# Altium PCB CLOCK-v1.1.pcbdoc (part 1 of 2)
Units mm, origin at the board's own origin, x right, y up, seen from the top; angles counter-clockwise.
Board outline 180 x 92.5 mm, 2 copper layers (Top Layer, Bottom Layer); 120 components, 111 nets, 414 pads, 6 vias.
Unrouted connection lines stored in the file: 2.
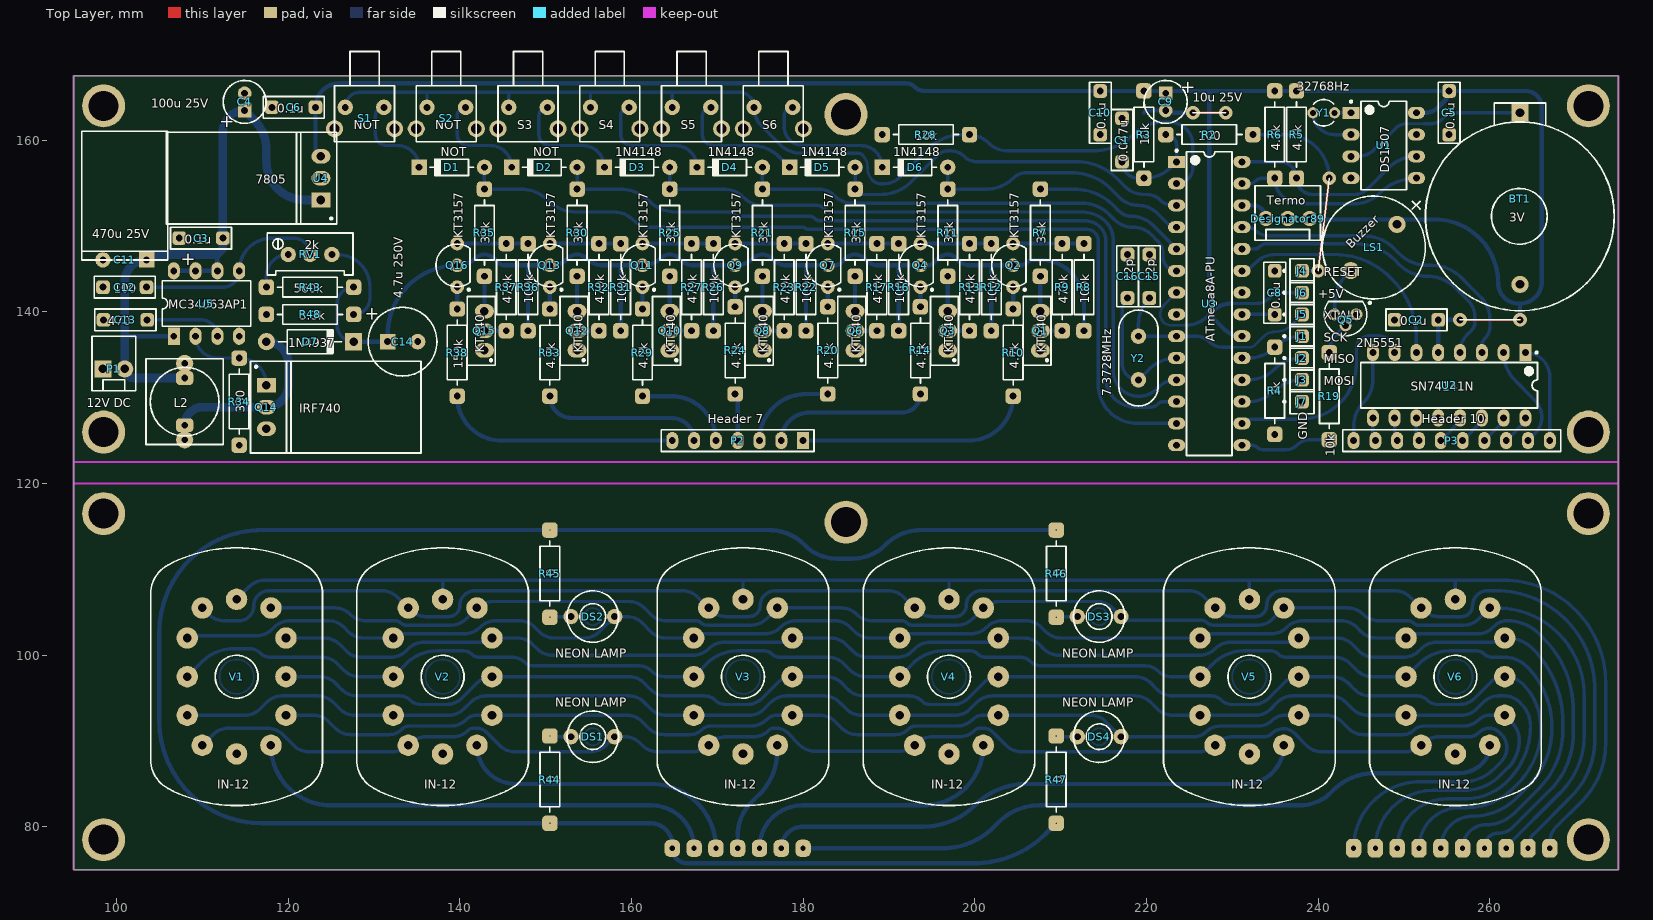
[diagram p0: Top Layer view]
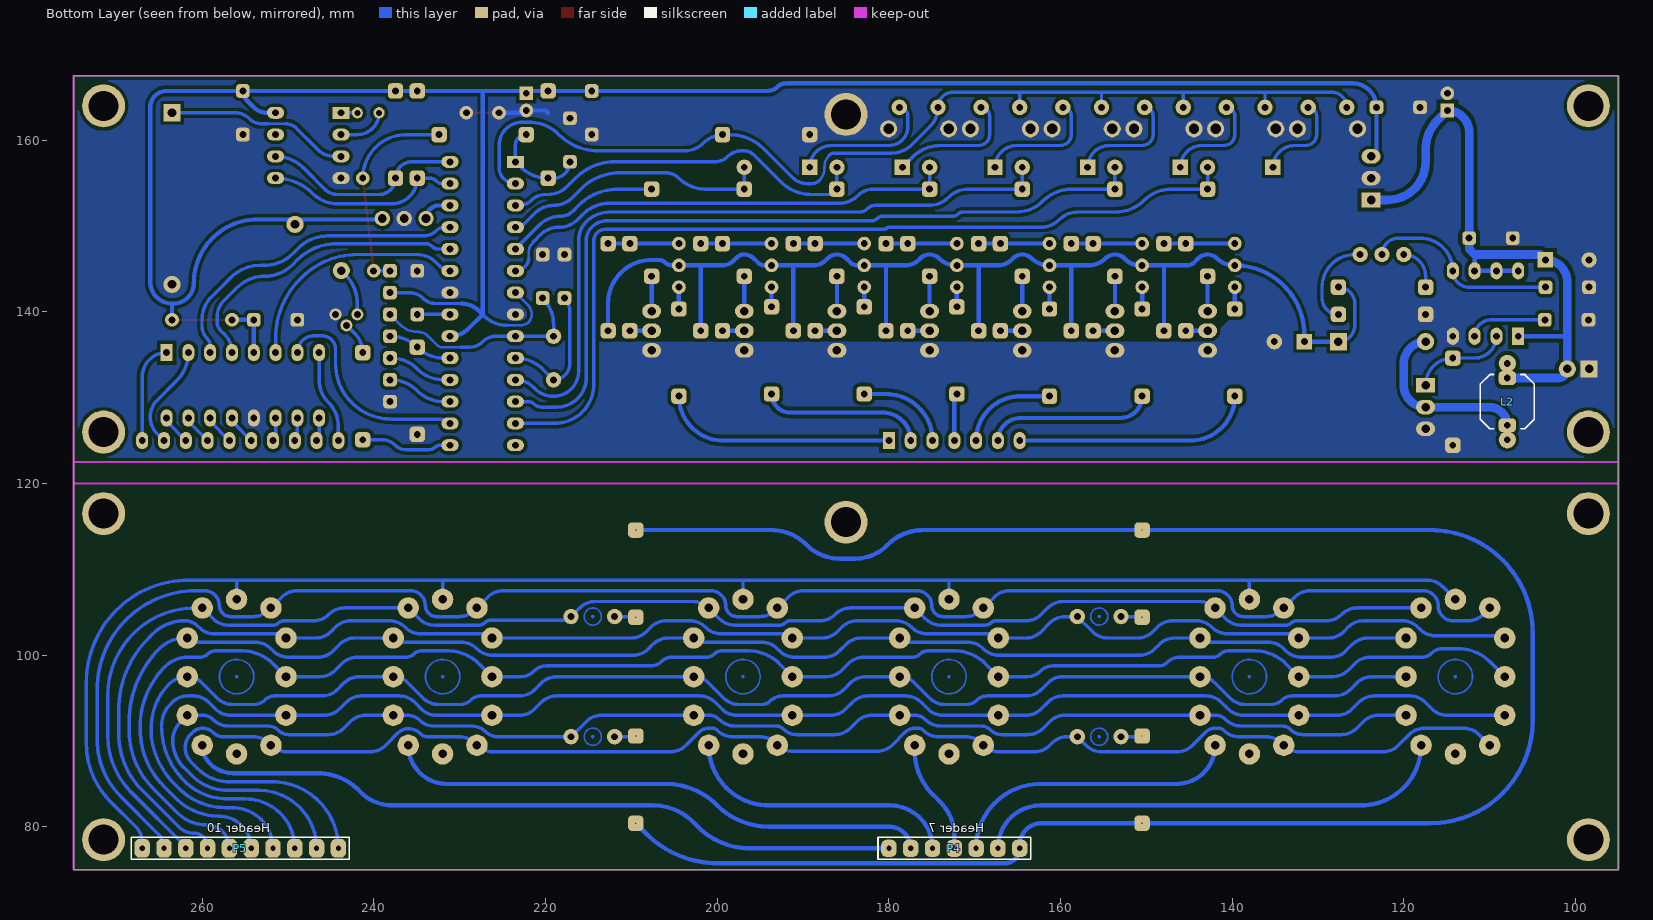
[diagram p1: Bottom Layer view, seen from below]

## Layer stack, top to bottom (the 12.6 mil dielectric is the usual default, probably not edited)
Top Layer: signal copper 0.0356
Dielectric: dielectric 0.32, FR-4, Dk 4.8
Bottom Layer: signal copper 0.0356

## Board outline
95,120 95,122.5 95,167.5 275,167.5 275,122.5 275,120 275,75 95,75

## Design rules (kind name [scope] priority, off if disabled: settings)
Clearance [InNet('+12V')] p1: gap=0.5
Clearance Clearance_PAD [All] p2: gap=0.4
ComponentClearance ComponentClearance_VD1_GB1 [(InComponent('GB1','VD1') ) vs IsComponentBody] p1: gap=0 collisioncheckmode=3 verticalgap=0 showdistances=FALSE
ComponentClearance ComponentClearance_Case [IsComponentBody vs IsComponentBody] p2: gap=0 collisioncheckmode=3 verticalgap=0 showdistances=FALSE
ComponentClearance [All] p3: gap=1 collisioncheckmode=3 verticalgap=0 showdistances=FALSE
FabricationTestPointUsage TestPointUsage [All] p1: valid=0 allowmultiple=FALSE
FabricationTestpoint Testpoint [All] p1: side=3 testpointundercomponent=TRUE minsize=1.016 maxsize=2.54 preferedsize=1.524 minholesize=0 maxholesize=1.016 preferedholesize=0.813 testpointgrid=0.025 allowsidetop=TRUE allowsidebottom=TRUE usegrid=TRUE gridtolerance=0
PlaneClearance PlaneClearance_1 [InPolygon] p1: clearance=0.508
PlaneClearance [All] p2: clearance=0.508
PolygonConnect [All] p1: connectstyle=Direct reliefconductorwidth=0.4 reliefentries=4 polygonreliefangle="90 Angle"
RoutingVias [All] p1: holewidth=0.711 width=1.27 viastyle="Through Hole" minholewidth=0.711 minwidth=1.27 maxholewidth=0.711 maxwidth=1.27
SilkscreenOverComponentPads [All] p1: minsilkscreentomaskgap=0.254
SolderMaskExpansion [All] p1: expansion=0.102
Width [All] p1: maxlimit=254 minlimit=0.254 preferedwidth=0.254
23 further rules are at their usual default settings.

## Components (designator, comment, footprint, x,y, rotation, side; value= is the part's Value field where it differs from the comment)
BT1 "3V" BH20D66 263.525,163.195 r0 top
C1 "0.047u" "WIMA 47/1000" 217.17,162.56 r270 top
C2 "0.1u" "WIMA 47/1000" 248.92,139.065 r0 top
C3 "0.1u" "WIMA 47/1000" 107.315,148.59 r0 top
C4 "100u 25V" "CAP 2-5X11" 114.935,164.465 r90 top
C5 "0.1u" "WIMA 47/1000" 255.27,160.655 r90 top
C6 "0.1u" "WIMA 47/1000" 118.11,163.83 r0 top
C8 "0.1u" "WIMA 47/1000" 234.95,144.78 r270 top
C9 "10u 25V" "CAP 2-5X11" 222.25,164.465 r270 top
C10 "0.1u" "WIMA 47/1000" 214.63,160.655 r90 top
C11 "470u 25V" "CAP 5-13x21" 100.965,146.05 r180 top
C12 "100" "WIMA 47/1000" 98.425,142.875 r0 top
C13 "470" "WIMA 47/1000" 98.5,139.065 r0 top
C14 "4.7u 250V" "CAP 3.5-8x12" 133.35,136.525 r0 top
C15 "22p" "WIMA 47/1000" 220.345,141.605 r90 top
C16 "22p" "WIMA 47/1000" 217.805,141.605 r90 top
D1 "NOT" DO-35 139.065,156.845 r180 top
D2 "NOT" DO-35 149.86,156.845 r180 top
D3 "1N4148" DO-35 160.655,156.845 r180 top
D4 "1N4148" DO-35 171.45,156.845 r180 top
D5 "1N4148" DO-35 182.245,156.845 r180 top
D6 "1N4148" DO-35 193.04,156.845 r180 top
D7 "1N4937" DO-41 122.555,136.525 r0 top
Designator89 "Termo" HU-03F 236.474,150.876 r180 top
DS1 "NEON LAMP" NEON_1 155.5,90.5 r180 top
DS2 "NEON LAMP" NEON_1 155.5,104.5 r180 top
DS3 "NEON LAMP" NEON_1 214.5,104.5 r180 top
DS4 "NEON LAMP" NEON_1 214.5,90.5 r180 top
J1 "SCK" PIN1 238.125,137.16 r90 top
J2 "MISO" PIN1 238.125,134.62 r90 top
J3 "MOSI" PIN1 238.125,132.08 r90 top
J4 "RESET" PIN1 238.125,144.78 r90 top
J5 "XTAL1" PIN1 238.125,139.7 r90 top
J6 "+5V" PIN1 238.125,142.24 r90 top
J7 "GND" PIN1 238.125,129.54 r90 top (schematic designator J4)
L2 "B82462G4334M000" B82462G4 107.95,129.54 r270 bottom
LS1 "Buzzer" BUZZER_1 246.5,147.5 r225 top
P1 "12V DC" HU-02F 100.965,133.35 r180 top
P2 "Header 7" HDR1X7#1 180,125 r180 top
P3 "Header 10" HDR1X10#1 267,125 r180 top
P4 "Header 7" HDR1X7#2 180,77.5 r180 bottom
P5 "Header 10" HDR1X10#2 267,77.5 r180 bottom
Q1 "KT940" TO-126 207.645,137.795 r90 top
Q2 "KT3157" TO-92B 204.47,145.415 r0 top
Q3 "KT940" TO-126 196.85,137.795 r90 top
Q4 "KT3157" TO-92B 193.675,145.415 r0 top
Q5 "2N5551" TO-92A 243.205,139.7 r90 top
Q6 "KT940" TO-126 186.055,137.795 r90 top
Q7 "KT3157" TO-92B 182.88,145.415 r0 top
Q8 "KT940" TO-126 175.26,137.795 r90 top
Q9 "KT3157" TO-92B 172.085,145.415 r0 top
Q10 "KT940" TO-126 164.465,137.795 r90 top
Q11 "KT3157" TO-92B 161.29,145.415 r0 top
Q12 "KT940" TO-126 153.67,137.795 r90 top
Q13 "KT3157" TO-92B 150.495,145.415 r0 top
Q14 "IRF740" TO-220AB 117.475,128.905 r270 top
Q15 "KT940" TO-126 142.875,137.795 r90 top
Q16 "KT3157" TO-92B 139.7,145.415 r0 top
R2 "100" MF-0.25#1 227.33,160.655 r180 top
R3 "10k" MF-0.25#1 219.71,160.655 r270 top
R4 "3k" MF-0.25#1 234.95,130.81 r270 top
R5 "4.7k" MF-0.25#1 237.49,160.655 r90 top
R6 "4.7k" MF-0.25#1 234.95,160.655 r90 top
R7 "33k" MF-0.25#1 207.645,149.225 r270 top
R8 "100k" MF-0.25#1 212.725,142.875 r90 top
R9 "470k" MF-0.25#1 210.185,142.875 r270 top
R10 "4.7k" MF-0.25#1 204.47,135.255 r270 top
R11 "33k" MF-0.25#1 196.85,149.225 r270 top
R12 "100k" MF-0.25#1 201.93,142.875 r270 top
R13 "470k" MF-0.25#1 199.39,142.875 r90 top
R14 "4.7k" MF-0.25#1 193.675,135.509 r90 top
R15 "33k" MF-0.25#1 186.055,149.225 r270 top
R16 "100k" MF-0.25#1 191.135,142.875 r270 top
R17 "470k" MF-0.25#1 188.595,142.875 r90 top
R19 "10k" MF-0.25#1 241.3,130.175 r270 top
R20 "4.7k" MF-0.25#1 182.88,135.509 r90 top
R21 "33k" MF-0.25#1 175.26,149.225 r270 top
R22 "100k" MF-0.25#1 180.34,142.875 r270 top
R23 "470k" MF-0.25#1 177.8,142.875 r90 top
R24 "4.7k" MF-0.25#1 172.085,135.509 r90 top
R25 "33k" MF-0.25#1 164.465,149.225 r270 top
R26 "100k" MF-0.25#1 169.545,142.875 r270 top
R27 "470k" MF-0.25#1 167.005,142.875 r90 top
R28 "10k" MF-0.25#1 194.31,160.655 r0 top
R29 "4.7k" MF-0.25#1 161.29,135.255 r90 top
R30 "33k" MF-0.25#1 153.67,149.225 r270 top
R31 "100k" MF-0.25#1 158.75,142.875 r270 top
R32 "470k" MF-0.25#1 156.21,142.875 r90 top
R33 "4.7k" MF-0.25#1 150.495,135.255 r90 top
R34 "330" MF-0.25#1 114.3,129.54 r90 top
R35 "33k" MF-0.25#1 142.875,149.225 r270 top
R36 "100k" MF-0.25#1 147.955,142.875 r270 top
R37 "470k" MF-0.25#1 145.415,142.875 r90 top
R38 "150k" MF-0.25#1 139.7,135.255 r90 top
R43 "560k" MF-0.25#1 122.555,142.875 r0 top
R44 "0" MF-0.25#2 150.5,85.5 r270 top
R45 "0" MF-0.25#2 150.5,109.5 r90 top
R46 "0" MF-0.25#2 209.5,109.5 r90 top
R47 "0" MF-0.25#2 209.5,85.5 r270 top
R48 "3.3k" MF-0.25#1 122.555,139.7 r180 top
RV1 "2k" 3296W 122.555,146.685 r180 top
S1 "NOT" SWT-3 128.905,163.83 r180 top
S2 "NOT" SWT-3 138.43,163.83 r180 top
S3 "SW-PB" SWT-3 147.955,163.83 r180 top
S4 "SW-PB" SWT-3 157.48,163.83 r180 top
S5 "SW-PB" SWT-3 167.005,163.83 r180 top
S6 "SW-PB" SWT-3 176.53,163.83 r180 top
U1 "DS1307" DIP8 247.65,159.385 r0 top
U2 "SN74141N" DIP16 255.27,131.445 r270 top
U3 "ATmega8A-PU" 28P3 227.33,140.97 r0 top
U4 "7805" TO-220AB 123.825,155.575 r90 top
U5 "MC34063AP1" 626-05 110.49,140.97 r0 top
V1 "IN-12" IN-12 114,97.5 r0 top
V2 "IN-12" IN-12 138,97.5 r0 top
V3 "IN-12" IN-12 173,97.5 r0 top
V4 "IN-12" IN-12 197,97.5 r0 top
V5 "IN-12" IN-12 232,97.5 r0 top
V6 "IN-12" IN-12 256,97.5 r0 top
Y1 "32768Hz" R38 240.665,163.195 r270 top
Y2 "7.3728MHz" HC-49 219.075,134.62 r90 top

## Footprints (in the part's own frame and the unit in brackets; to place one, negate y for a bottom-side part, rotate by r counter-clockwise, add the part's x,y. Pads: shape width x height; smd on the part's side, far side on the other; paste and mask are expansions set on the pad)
28P3 [mm] "DIP, 28-Leads, Row Spacing 7.62mm, Pitch 2.54mm, Body 34.67x7.3mm"
  rect 2x1.4 hole 0.8: 1(-3.81,16.51)
  oval 2x1.4 hole 0.8: 2(-3.81,13.97) 3(-3.81,11.43) 4(-3.81,8.89) 5(-3.81,6.35) 6(-3.81,3.81) 7(-3.81,1.27) 8(-3.81,-1.27) 9(-3.81,-3.81) 10(-3.81,-6.35) 11(-3.81,-8.89) 12(-3.81,-11.43) 13(-3.81,-13.97) 14(-3.81,-16.51) 15(3.81,-16.51) 16(3.81,-13.97) 17(3.81,-11.43) 18(3.81,-8.89) 19(3.81,-6.35) 20(3.81,-3.81) 21(3.81,-1.27) 22(3.81,1.27) 23(3.81,3.81) 24(3.81,6.35) 25(3.81,8.89) 26(3.81,11.43) 27(3.81,13.97) 28(3.81,16.51)
  silkscreen extent -3.93,-17.7 2.65,17.93, body extent -3.6,-17.65 3.6,17.65, height 4.58
626-05 [mm] "DIP; 8 Leads; Row Spacing 7.62 mm; Pitch 2.54 mm"
  rect 1.4x2 hole 0.8: 1(-3.81,-3.81)
  oval 1.4x2 hole 0.8: 2(-1.27,-3.81) 3(1.27,-3.81) 4(3.81,-3.81) 5(3.81,3.81) 6(1.27,3.81) 7(-1.27,3.81) 8(-3.81,3.81)
  silkscreen extent -5.15,-2.65 5.15,2.65
3296W [mm] "Resistor, Variavle, Thru-Hole, Vertical, 3 In-Line Leads; Pitch 2.54 mm"
  round 1.8 hole 0.8: 1(2.54,0) 2(0,0) 3(-2.54,0)
  silkscreen extent -5,-2.5 5,2.4
B82462G4 [mm] "SM Inductor; 2 Leads; Body 6.3x6.3mm (LxW)"
  rrect50% 1.6x2 hole 0.8: 1(-2.75,0) 2(2.75,0)
  silkscreen extent -3.15,-3.15 3.15,3.15, body extent -3.15,-3.15 3.15,3.15, height 3
BH20D66 [mm]
  rect 2x2 hole 1: 1(0,0)
  round 2 hole 1: 2(0,-20)
  silkscreen extent -11.02,-23.07 10.98,1.14
BUZZER_1 [mm] "BUZZER, 12mm, Pitch 7.62mm"
  round 2 hole 1: 1(-3.81,0) 2(3.81,0)
  silkscreen extent -7.62,-6 6,6
"CAP 2-5X11" [mm] "Capacitor, Electrolytic, Radial"
  rect 1.6x1.6 hole 0.8: 1(-1,0)
  round 1.6 hole 0.8: 2(1,0)
  silkscreen extent -2.5,-2.5 2.5,2.5
"CAP 3.5-8x12" [mm] "Capacitor, Electrolytic, Radial"
  rect 1.8x1.8 hole 0.8: 1(-1.75,0)
  round 1.8 hole 0.8: 2(1.75,0)
  silkscreen extent -4.02,-4 3.98,4
"CAP 5-13x21" [mm] "Capacitor, Electrolytic, Radial"
  rect 1.8x1.8 hole 0.8: 1(-2.54,0)
  round 1.8 hole 0.8: 2(2.54,0)
DIP8 [mm] "DIP, 8-Leads, Row Spacing 7.62mm, Pitch 2.54mm, Body 9.65x6.35mm"
  rect 2x1.4 hole 0.8: 1(-3.81,3.81)
  oval 2x1.4 hole 0.8: 2(-3.81,1.27) 3(-3.81,-1.27) 4(-3.81,-3.81) 5(3.81,-3.81) 6(3.81,-1.27) 7(3.81,1.27) 8(3.81,3.81)
  silkscreen extent -3.93,-5.15 2.65,5.23, body extent -3.6,-5.15 3.6,5.15, height 4.42
DIP16 [mm] "DIP; 16 Leads; Row Spacing 7.62 mm; Pitch 2.54 mm"
  rect 2x1.4 hole 0.8: 1(-3.81,8.89)
  oval 2x1.4 hole 0.8: 2(-3.81,6.35) 3(-3.81,3.81) 4(-3.81,1.27) 5(-3.81,-1.27) 6(-3.81,-3.81) 7(-3.81,-6.35) 8(-3.81,-8.89) 9(3.81,-8.89) 10(3.81,-6.35) 11(3.81,-3.81) 12(3.81,-1.27) 13(3.81,1.27) 14(3.81,3.81) 15(3.81,6.35) 16(3.81,8.89)
  silkscreen extent -3.93,-10.3 2.65,10.32, body extent -3.6,-10.28 3.6,10.28, height 5.08
DO-35 [mm] "Diode, Axial; Body 3.8 x 1.9 mm (LxDia. max), Lead Dia. 0.53 mm (max)"
  round 1.8 hole 0.8: 1(-3.81,0)
  rect 1.8x1.8 hole 0.8: 2(3.81,0)
  silkscreen extent -2.54,-1.02 2.54,1.02
DO-41 [mm] "Diode, Axial; Body 5.2 x 2.7 mm (LxDia. max), Lead Dia. 0.86 mm (max)"
  round 2 hole 1: 1(-5.08,0)
  rect 2x2 hole 1: 2(5.08,0)
  silkscreen extent -3.68,-1.4 3.68,1.4
HC-49 [mm] "XTAL"
  round 1.8 hole 0.8: 1(-2.54,0) 2(2.54,0)
  silkscreen extent -5.59,-2.29 5.59,2.29
HDR1X7#1 [mm] "Connector; Header; 7 Position"
  rect 1.4x2 hole 0.8: 1(0,0)
  oval 1.4x2 hole 0.8: 2(2.54,0) 3(5.08,0) 4(7.62,0) 5(10.16,0) 6(12.7,0) 7(15.24,0)
  silkscreen extent -1.27,-1.27 16.51,1.27
HDR1X7#2 [mm] "Connector; Header; 7 Position"
  rrect70% 1.8x2 hole 0.6: 1(0,0) 2(2.54,0) 3(5.08,0) 4(7.62,0) 5(10.16,0) 6(12.7,0) 7(15.24,0)
  silkscreen extent -1.27,-1.27 16.51,1.27
HDR1X10#1 [mm] "Connector; Header; 10 Position"
  oval 1.4x2 hole 0.8: 1(0,0) 2(2.54,0) 3(5.08,0) 4(7.62,0) 5(10.16,0) 6(12.7,0) 7(15.24,0) 8(17.78,0) 9(20.32,0) 10(22.86,0)
  silkscreen extent -1.27,-1.27 24.13,1.27
HDR1X10#2 [mm] "Connector; Header; 10 Position"
  rrect70% 1.8x2.2 hole 0.6: 1(0,0) 2(2.54,0) 3(5.08,0) 4(7.62,0) 5(10.16,0) 6(12.7,0) 7(15.24,0) 8(17.78,0) 9(20.32,0) 10(22.86,0)
  silkscreen extent -1.27,-1.27 24.13,1.27
HU-02F [mm] "Connector; Header; 2 Position"
  round 2 hole 1: 1(0,0)
  rect 2x2 hole 1: 2(2.54,0)
  silkscreen extent -1.27,-3.81 3.81,2.54
HU-03F [mm] "Connector; Header; 3 Position"
  round 1.8 hole 1: 1(-2.54,0) 2(0,0) 3(2.54,0)
  silkscreen extent -3.81,-3.81 3.81,2.54
IN-12 [mm] "Vacuum Indicator"
  round 2.5 hole 1: 1(4.001,-8.002) 2(5.751,-4.501) 3(5.751,0) 4(5.751,4.501) 5(4.001,8.002) 6(0,9.002) 7(-4.001,8.002) 8(-5.751,4.501) 9(-5.751,0) 10(-5.751,-4.501) 11(-4.001,-8.002) 12(0,-9.002)
  silkscreen extent -10,-15.03 10,15
MF-0.25#1 [mm] "Resistor; 2 Leads"
  rrect50% 1.8x1.8 hole 0.8: 1(-5.08,0) 2(5.08,0)
  silkscreen extent -3.81,-1.14 3.81,1.14
MF-0.25#2 [mm] "Resistor; 2 Leads"
  rrect50% 1.8x1.8 hole 0.1: 1(-5.08,0) 2(5.08,0)
  silkscreen extent -3.81,-1.14 3.81,1.14
NEON_1 [mm] "6mm, Pitch 5.08mm"
  round 1.8 hole 0.8: 1(-2.54,0) 2(2.54,0)
  silkscreen extent -3,-3 3,3
PIN1 [mm] "Connector; Plug"
  rrect50% 1.6x1.6 hole 0.8: 1(0,0)
  silkscreen extent -1.4,-1.4 1.4,2.17
R38 [mm] "Crystal, Thru-Hole; 2 Leads; Body 3.1 x 8.2 mm (Dia.xH)"
  round 1.3 hole 0.7: 1(0,1.27) 2(0,-1.27)
  silkscreen extent -1.55,-1.19 1.55,1.17
SWT-3 [mm] "Micro Button,"
  round 1.8 hole 0.8: 1(-2.25,0) 3(2.25,0)
  round 2 hole 1.2: 5(-3.5,2.5) 6(3.5,2.5)
  silkscreen extent -3.5,-6.5 3.5,4
TO-92A [mm] "TO, Flat Index; 3 In-Line, Axial Leads; Body Dia. 4.5mm; Leads 0.51 x 0.48 mm (max)"
  round 1.4 hole 0.8: 1(0,-1.27) 2(-1.27,0) 3(0,1.27)
  silkscreen extent -2.48,-2.96 1.5,2.48, body extent -2.5,-2.5 1.5,2.5, height 6.86
TO-92B [mm] "TO, Flat Index; 3 In-Line, Axial Leads; Body Dia. 4.5mm; Leads 0.51 x 0.48 mm (max)"
  round 1.6 hole 0.8: 1(0,-2.54) 2(0,0) 3(0,2.54)
  silkscreen extent -2.48,-2.95 1.5,2.48, body extent -2.5,-2.5 1.5,2.5, height 6.86
TO-126 [mm] "TO, Thru-Hole, Vertical, Heatsink Mounted; 3 In-Line Leads; Pitch 2.54 mm"
  oval 1.7x2.2 hole 1: 1(-2.286,0) 2(0,0) 3(2.286,0)
  silkscreen extent -4,-1.25 4,2
TO-220AB [mm] "TO, Thru-Hole, Vertical, Heatsink Mounted; 3 In-Line Leads; Pitch 2.54 mm"
  rect 1.7x2.2 hole 1: 1(-2.54,0)
  oval 1.7x2.2 hole 1: 2(0,0) 3(2.54,0)
  silkscreen extent -5.35,-1.85 5.35,2.85, body extent -5.4,-1.9 5.4,2.9, height 19.3
"WIMA 47/1000" [mm] "Capasitor"
  rrect50% 1.6x1.6 hole 0.8: 1(0,0) 2(5.08,0)
  silkscreen extent -1.02,-1.27 6.1,1.27

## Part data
BT1: library part BATTERY_1, "Battery"
C1 C2 C3 C5 C6 C8 C10 C12 C13 C15 C16: library part CAP, "Capacitor"
C4 C9: library part CAP_10uFx25V, "Polarized Capacitor (Radial)"
C11: library part CAP_470uFx63V, "Polarized Capacitor (Radial)"
C14: library part CAP_100uFx50V, "Polarized Capacitor (Radial)"
D1 D2: library part 1N4148, "High Conductance Fast Diode"
D3 D4 D5 D6: "High Conductance Fast Diode"
D7: library part 1N4007, "1 Amp General Purpose Rectifier"
DS1 DS2 DS3 DS4: "Neon Lamp"
J1 J2 J3 J4 J5 J6 J7: library part Socket, "Socket"
L2: "SMT Power Inductor; Size 6.3Ч6.3Ч3.0mm, ±20% Tolerance, 330uH, 0.27A"
LS1: library part BUZZER, "Magnetic Transducer Buzzer"
P1: library part HU-02F, "Header, 2-Pin"
P2 P4: "Header, 7-Pin"
P3 P5: "Header, 10-Pin"
Q1 Q3 Q6 Q8 Q10 Q12 Q15: library part BD139, "NPN General Purpose Amplifier"
Q2 Q4 Q7 Q9 Q11 Q13 Q16: "High Voltage Transistor PNP Silicon"
Q5: "NPN General Purpose Amplifier"
Q14: "HEXFET N-Channel Power MOSFET"
R2 R3 R4 R5 R6 R7 R8 R9 R10 R11 R12 R13 R14 R15 R16 R17 R19 R20 R21 R22 R23 R24 R25 R26 R27 R28 R29 R30 R31 R32 R33 R34 R35 R36 R37 R38 R43 R44 R45 R46 R47 R48: library part RES-0.25, "Resistor"
RV1: library part RES_VAR_2, "Resistor Variable, Single"
S1 S2: library part SW-PB, "Push Button"
S3 S4 S5 S6: "Push Button"
U1: "64 X 8 Serial Real-Time Clock"
U2: "BCD-to-Decimal Decoder"
U3: "8-bit AVR Microcontroller, 8KB Flash, 512 Bytes EEPROM, 1KB SRAM, 28-pin PDIP, Industrial Grade (-40°C to 85°C)"
U4: library part 78xx, "Precision 1A Regulator"
U5: "DC-to-DC Converter Control Circuit"
V1 V2 V3 V4 V5 V6: "Vacuum Indicator"
Y1 Y2: library part XTAL, "Crystal Oscillator"

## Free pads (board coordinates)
  round 5 hole 3.5: 0(98.5,164) 1(98.5,126) 2(271.5,126) 3(271.5,164) 4(98.5,116.5) 5(98.5,78.5) 6(271.5,78.5) 7(271.5,116.5) 8(185,115.5) 10(185,163)
  round 2 hole 0.8: 0(107.95,133.985) 1(107.95,125.095)

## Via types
v1: diameter 1.6, hole 0.8, Top Layer to Bottom Layer, 6 vias

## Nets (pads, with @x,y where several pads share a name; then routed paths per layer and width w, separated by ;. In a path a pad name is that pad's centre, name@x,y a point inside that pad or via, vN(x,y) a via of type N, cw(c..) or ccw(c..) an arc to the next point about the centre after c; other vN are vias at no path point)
+5V: C2.2 C5.2 C6.2 C9.1 C10.2 Designator89.1 J6.1 LS1.1 R3.1 R5.2 R6.2 U1.8 U2.5 U3.7 U3.20 U4.3 | length 289.4
  Top Layer w0.254: v1(256.54,139.065) v1(263.525,139.065)
  Bottom Layer w0.3: U3.7@223.52,142.24 222.064,140.784 ccw(c223.148,139.7) 221.615,139.7 ccw(c222.885,139.7) 222.885,138.43 223.52,138.43 224.79,138.43 ; 224.155,138.43 224.536,138.43 ; 229.87,140.97 232.41,140.97
  Bottom Layer w0.4: 224.536,138.43 ccw(c224.536,142.109) 227.138,139.508 227.33,139.7 228.972,138.058 ; 232.41,140.97 232.782,140.97 ccw(c232.782,143.138) 234.315,141.605 cw(c235.848,140.072) 235.848,142.24 J6.1@238.125,142.24 ; 228.972,138.058 ccw(c231.14,140.226) U3.20@231.14,137.16 cw(c231.14,140.226) 228.972,138.058
  Bottom Layer w0.5: U4.3@123.825,158.115 123.19,158.75 C6.2@123.19,163.83 cw(c125.984,163.83) 125.984,166.624 191.97,166.624 ; 229.87,140.97 ccw(c229.87,137.904) 227.702,140.072 227.33,139.7 ; U3.20@231.14,137.16 cw(c231.14,140.226) 228.972,138.058 227.33,139.7 ; Designator89.1@239.014,150.876 239.119,150.771 249.98,150.771 253.565,150.771 cw(c253.565,143.351) 260.985,143.351 ccw(c263.366,143.351) 263.366,140.97 263.525,140.97 ; U1.8@251.46,163.195 252.467,163.195 ccw(c252.467,165.363) 254,163.83 254.821,164.651 ccw(c253.737,165.735) C5.2@255.27,165.735 ; U2.5@254,135.255 C2.2@254,139.065 255.27,139.065 v1(256.54,139.065) ; 256.54,165.735 C5.2@255.27,165.735 ; v1(263.525,139.065) 263.525,140.97 ; 191.97,166.624 cw(c191.97,165.111) 193.04,166.181 ; 191.97,166.624 cw(c191.97,165.111) 193.04,166.181 ; 193.04,166.181 ccw(c194.117,167.258) 194.117,165.735 R3.1@219.71,165.735 221.98,165.735 C9.1@222.25,165.465 222.52,165.735 227.33,165.735 ; 227.33,139.7 227.33,165.735 ; 227.33,165.735 R6.2@234.95,165.735 R5.2@237.49,165.735 254,165.735 C5.2@255.27,165.735 ; C5.2@255.27,165.735 264.16,165.735 cw(c264.16,163.83) 266.065,163.83 266.065,143.51 cw(c263.525,143.51) 263.525,140.97
+12V: C3.2 C4.1 C11.1 L2.1 P1.1 pad.0@107.95,133.985 U4.1 U5.1 U5.6 U5.7 U5.8 | length 86.1
  Bottom Layer w0.4: 101.04,137.16 101.04,143.585 ; C11.1@103.505,146.05 103.54,146.5 C11.1@103.955,146.5
  Bottom Layer w0.5: 101.04,137.16 U5.1@106.68,137.16 ; C11.1@103.505,146.05 C11.1@103.955,146.5 ; U5.8@106.68,144.78 U5.7@109.22,144.78 U5.6@111.76,144.78 111.76,146.685
  Bottom Layer w1: C11.1@103.505,146.05 ccw(c103.505,143.51) 100.965,143.51 P1.1@100.965,133.35 ccw(c102.025,133.35) 102.025,132.29 L2.1@107.95,132.29 pad.0@107.95,133.985 ; C11.1@103.955,146.5 104.14,146.685 111.76,146.685 112.395,147.32 C3.2@112.395,148.59 112.395,160.925 cw(c114.935,160.925) 114.059,163.309 cw(c114.935,160.925) C4.1@114.935,163.465 116.061,162.339 cw(c112.649,158.926) 117.475,158.926 117.475,157.48 ccw(c121.92,157.48) 121.92,153.035 U4.1@123.825,153.035
+170V: C14.1 D7.2 Q2.2 Q4.2 Q7.2 Q9.2 Q11.2 Q13.2 Q16.2 R8.1 R12.2 R16.2 R22.2 R26.2 R31.2 R36.2 R43.2 | length 160.1
  Bottom Layer w0.4: D7.2@127.635,136.525 cw(c127.635,138.43) 125.73,138.43 125.73,140.97 cw(c127.635,140.97) R43.2@127.635,142.875
  Bottom Layer w0.5: D7.2@127.635,136.525 129.54,136.525 C14.1@131.6,136.525 131.6,137.315 cw(c139.7,137.315) Q16.2@139.7,145.415 139.809,145.415 ccw(c139.809,148.218) 141.791,146.236 cw(c142.875,145.152) 142.875,146.685 cw(c142.875,145.152) 143.959,146.236 144.463,145.732 ccw(c145.229,146.499) 145.229,145.415 147.955,145.415 ; R36.2@147.955,137.795 147.955,145.415 ; R31.2@158.75,137.795 158.75,145.415 ; R26.2@169.545,137.795 169.545,145.415 ; R22.2@180.34,137.795 180.34,145.415 ; R16.2@191.135,137.795 191.135,145.415 ; R12.2@201.93,137.795 201.93,145.415 ; R8.1@212.725,137.795 212.725,140.97 ccw(c207.645,140.97) 207.645,146.05 206.824,146.05 ccw(c206.824,144.966) 206.058,145.732 cw(c205.291,146.499) 205.291,145.415 Q2.2@204.47,145.415 201.93,145.415 ; 147.955,145.415 Q13.2@150.495,145.415 Q13.2@150.604,145.415 ; Q13.2@150.604,145.415 ccw(c150.604,148.218) 152.392,146.059 ; Q13.2@150.604,145.415 150.836,145.415 ccw(c150.836,147.615) 152.392,146.059 ; 152.392,146.059 ccw(c150.604,148.218) 152.586,146.236 cw(c153.67,145.152) 153.67,146.685 ; 152.392,146.059 152.556,146.224 cw(c153.67,145.11) 153.67,146.685 ; 153.67,146.685 cw(c153.67,145.152) 154.754,146.236 ; 153.67,146.685 cw(c153.67,145.152) 154.754,146.236 ; 154.754,146.236 ccw(c156.736,148.218) 154.756,146.234 ; 154.754,146.236 154.756,146.234 ; 154.756,146.234 ccw(c156.736,148.218) 156.736,145.415 158.75,145.415 ; 158.75,145.415 Q11.2@161.29,145.415 161.399,145.415 ccw(c161.399,148.218) 163.381,146.236 cw(c164.465,145.152) 164.465,146.685 cw(c164.465,145.152) 165.549,146.236 165.735,146.05 ccw(c167.268,147.583) 167.268,145.415 169.545,145.415 ; 169.545,145.415 Q9.2@172.085,145.415 172.194,145.415 ccw(c172.194,148.218) 174.176,146.236 cw(c175.26,145.152) 175.26,146.685 cw(c175.26,145.152) 176.344,146.236 176.53,146.05 ccw(c178.063,147.583) 178.063,145.415 180.34,145.415 ; 180.34,145.415 Q7.2@182.88,145.415 183.701,145.415 ccw(c183.701,146.499) 184.467,145.733 184.971,146.236 cw(c186.055,145.152) 186.055,146.685 cw(c186.055,145.152) 187.139,146.236 187.39,145.985 ccw(c188.766,147.361) 188.766,145.415 191.135,145.415 ; 191.135,145.415 Q4.2@193.675,145.415 194.496,145.415 ccw(c194.496,146.499) 195.263,145.733 195.766,146.236 cw(c196.85,145.152) 196.85,146.685 cw(c196.85,145.434) 197.735,146.319 198.086,145.967 ccw(c199.42,147.301) 199.42,145.415 201.93,145.415
_Y1: P3.1 U2.1 | length 11.9
  Bottom Layer w0.4: U2.1@264.16,135.255 cw(c264.16,132.415) 267,132.415 P3.1@267,125
_Y2: P3.2 U2.2 | length 12.3
  Bottom Layer w0.4: U2.2@261.62,135.255 ccw(c266.219,135.255) 262.967,132.003 265.252,129.718 cw(c263.289,127.755) 266.065,127.755 cw(c263.289,127.755) 265.252,125.792 P3.2@264.46,125
_Y3: P3.3 U2.16 | length 3.6
  Bottom Layer w0.4: P3.3@261.92,125 264.16,127.24 U2.16@264.16,127.635
_Y4: P3.4 U2.15 | length 3.6
  Bottom Layer w0.4: P3.4@259.38,125 261.62,127.24 U2.15@261.62,127.635
_Y5: P3.5 U2.14 | length 3.6
  Bottom Layer w0.4: P3.5@256.84,125 259.08,127.24 U2.14@259.08,127.635
_Y6: P3.6 U2.13 | length 3.6
  Bottom Layer w0.4: P3.6@254.3,125 256.54,127.24 U2.13@256.54,127.635
_Y7: P3.7 U2.11 | length 2.8
  Bottom Layer w0.4: U2.11@251.46,127.635 251.46,125.3 P3.7@251.76,125
_Y8: P3.8 U2.10 | length 2.8
  Bottom Layer w0.4: U2.10@248.92,127.635 248.92,125.3 P3.8@249.22,125
_Y9: P3.9 U2.9 | length 2.8
  Bottom Layer w0.4: U2.9@246.38,127.635 246.38,125.3 P3.9@246.68,125
_Y10: P3.10 U2.8 | length 10.9
  Bottom Layer w0.4: P3.10@244.14,125 244.14,126.585 cw(c248.319,126.585) 245.364,129.54 ccw(c242.911,131.993) 246.38,131.993 U2.8@246.38,135.255
A1: U2.3 U3.25 | length 37.4
  Bottom Layer w0.4: U3.25@231.14,149.86 231.757,149.86 cw(c231.757,148.445) 232.758,149.446 ccw(c234.21,150.898) 234.21,148.844 245.397,148.844 cw(c245.397,144.018) 248.81,147.43 249.478,146.762 ccw(c252.73,150.014) 252.73,145.415 253.271,145.415 cw(c253.271,140.589) 256.684,144.001 257.81,142.875 258.91,141.775 cw(c256.2,139.065) 259.715,140.592 cw(c256.2,139.065) 260.032,139.065 260.032,138.376 cw(c257.864,138.376) 259.715,137.246 cw(c257.864,138.376) 259.398,136.843 cw(c257.864,138.376) 259.398,136.842 ccw(c260.164,136.076) 259.08,136.076 U2.3@259.08,135.255
A2: U2.6 U3.23 | length 28.2
  Bottom Layer w0.4: U3.23@231.14,144.78 ccw(c231.14,146.313) 232.224,145.229 232.782,145.787 cw(c234.95,143.619) 234.95,146.685 241.935,146.685 cw(c241.935,137.487) 248.439,143.991 248.602,143.827 cw(c241.704,136.929) 251.46,136.929 U2.6@251.46,135.255
A3: U2.7 U3.16 | length 25.3
  Bottom Layer w0.4: U3.16@231.14,127 cw(c232.366,125.774) 232.366,127.508 237.998,127.508 ccw(c237.998,133.985) 244.475,133.985 244.475,135.636 cw(c246.064,135.636) 246.064,137.225 246.95,137.225 cw(c246.95,135.255) U2.7@248.92,135.255
A4: U2.4 U3.24 | length 35.4
  Bottom Layer w0.4: U3.24@231.14,147.32 232.559,147.32 ccw(c232.559,148.187) 233.172,147.574 cw(c234.092,146.654) 234.092,147.955 244.321,147.955 cw(c244.321,141.451) 248.92,146.05 249.478,145.492 ccw(c252.73,148.744) 252.73,144.145 cw(c252.73,139.546) 255.982,142.798 257.49,141.29 cw(c255.582,139.382) 258.28,139.382 258.28,138.824 cw(c256.931,138.824) 257.885,137.87 257.714,137.699 257.41,137.395 ccw(c259.51,135.295) 256.54,135.295 U2.4@256.54,135.255
ADC: Designator89.3 U3.26 | length 3.7
  Bottom Layer w0.5: U3.26@231.14,152.4 232.41,152.4 cw(c232.41,150.876) Designator89.3@233.934,150.876
BUZZER: R19.2 U3.15 | length 10.6
  Bottom Layer w0.4: U3.15@231.14,124.46 232.305,124.46 cw(c232.305,123.593) 232.918,124.206 ccw(c233.531,124.819) 233.531,123.952 236.317,123.952 ccw(c236.317,125.63) 237.503,124.443 cw(c239.076,122.87) 239.076,125.095 R19.2@241.3,125.095
GND: BT1.2 C1.1 C2.1 C3.1 C4.2 C5.1 C6.1 C8.1 C9.2 C10.1 C11.2 C12.1 C13.1 C14.2 C15.2 C16.2 Designator89.2 J7.1 P1.2 pad.10 Q1.1 Q3.1 Q5.1 Q6.1 Q8.1 Q10.1 Q12.1 Q14.3 Q15.1 R4.2 R28.1 R34.1 R48.2 S1.5 S1.6 S2.5 S2.6 S3.5 S3.6 S4.5 S4.6 S5.5 S5.6 S6.5 S6.6 U1.4 U2.12 U3.8 U3.22 U4.2 U5.4 | length 9.1
  Top Layer w0.254: v1(225.425,163.195) v1(229.235,163.195)
  Bottom Layer w0.5: 219.71,163.195 219.98,163.465 C9.2@222.25,163.465 222.52,163.195 v1@224.79,163.195
KEYS: R28.2 S1.3 S2.3 S3.3 S4.3 S5.3 S6.3 U3.2 | length 123.9
  Bottom Layer w0.3: 186.944,158.242 cw(c185.59,156.888) 187.505,156.888 187.505,156.812 ccw(c189.654,156.812) 188.134,155.293
  Bottom Layer w0.4: S1.3@126.655,163.83 cw(c128.433,163.83) 128.433,165.608 136.144,165.608 ; S2.3@136.18,163.83 136.18,165.572 136.144,165.608 ; S3.3@145.705,163.83 145.705,165.445 145.542,165.608 ; S4.3@155.386,163.83 S4.3@155.23,163.83 155.23,165.572 155.194,165.608 ; S5.3@165.038,163.83 S5.3@164.755,163.83 164.755,165.445 164.592,165.608 ; 186.944,158.242 ccw(c186.331,157.629) 186.331,158.496 179.705,158.496 cw(c179.705,161.869) 177.32,159.484 175.203,161.601 cw(c177.433,163.83) S6.3@174.28,163.83 ccw(c172.502,163.83) 172.502,165.608 164.592,165.608 ; 188.134,155.292 ccw(c188.985,156.144) 188.985,154.94 189.484,154.94 ccw(c189.484,157.485) 191.283,155.685 194.643,159.045 cw(c198.438,155.251) 198.438,160.617 199.34,160.617 cw(c199.34,157.43) 201.594,159.684 ccw(c203.847,161.937) 203.847,158.75 213.841,158.75 ccw(c213.841,165.254) 218.44,160.655 cw(c221.941,157.154) 221.941,162.105 222.705,162.105 cw(c222.705,159.385) 225.425,159.385 225.425,156.845 cw(c223.52,156.845) U3.2@223.52,154.94 ; 136.144,165.608 145.542,165.608 ; 145.542,165.608 155.194,165.608 ; 155.194,165.608 164.592,165.608
MISO: J2.1 U3.18 | length 7.7
  Bottom Layer w0.4: U3.18@231.14,132.08 231.884,132.08 ccw(c231.884,136.416) 234.95,133.35 cw(c238.016,130.284) 238.016,134.62 J2.1@238.125,134.62
MOSI: J3.1 U3.17 | length 7.7
  Bottom Layer w0.4: U3.17@231.14,129.54 231.884,129.54 ccw(c231.884,133.876) 234.95,130.81 cw(c238.016,127.744) 238.016,132.08 J3.1@238.125,132.08
NetBT1_1: BT1.1 U1.3 | length 20.8
  Bottom Layer w0.3: 250.3,161.925 252.328,161.925
  Bottom Layer w0.4: U1.3@243.84,158.115 244.693,158.115 ccw(c244.693,160.655) 246.489,158.859 249.028,161.398 cw(c250.3,160.126) 250.3,161.925 ; 252.328,161.925 253.112,161.925 ccw(c253.112,163.888) 254.5,162.5 cw(c256.178,160.822) 256.178,163.195 BT1.1@262.89,163.195
NetC8_2: C8.2 U3.21 | length 3.8
  Bottom Layer w0.4: U3.21@231.14,139.7 C8.2@234.95,139.7
NetC12_2: C12.2 RV1.2 U5.5 | length 23.4
  Bottom Layer w0.4: C12.2@103.505,142.875 112.395,142.875 ccw(c112.395,144.78) U5.5@114.3,144.78 cw(c118.11,144.78) 118.11,148.59 120.65,148.59 cw(c120.65,146.685) RV1.2@122.555,146.685
NetC13_2: C13.2 U5.3 | length 9.3
  Bottom Layer w0.4: C13.2@103.58,139.065 109.855,139.065 cw(c109.855,137.16) U5.3@111.76,137.16
NetD1_2: D1.2 S1.1 | length 11
  Bottom Layer w0.4: S1.1@131.155,163.83 ccw(c131.155,162.85) 130.175,162.85 130.175,160.655 ccw(c131.445,160.655) 131.445,159.385 132.715,159.385 cw(c132.715,156.845) D1.2@135.255,156.845
NetD2_2: D2.2 S2.1 | length 12.3
  Bottom Layer w0.4: S2.1@140.68,163.83 ccw(c140.68,162.85) 139.7,162.85 139.7,160.655 ccw(c140.97,160.655) 140.97,159.385 143.51,159.385 cw(c143.51,156.845) D2.2@146.05,156.845
NetD3_2: D3.2 S3.1 | length 13.5
  Bottom Layer w0.4: S3.1@150.205,163.83 ccw(c150.205,162.85) 149.225,162.85 149.225,160.655 ccw(c150.495,160.655) 150.495,159.385 154.305,159.385 cw(c154.305,156.845) D3.2@156.845,156.845
NetD4_2: D4.2 S4.1 | length 14.8
  Bottom Layer w0.4: S4.1@159.73,163.83 ccw(c159.73,162.85) 158.75,162.85 158.75,160.655 ccw(c160.02,160.655) 160.02,159.385 165.1,159.385 cw(c165.1,156.845) D4.2@167.64,156.845
NetD5_2: D5.2 S5.1 | length 15.5
  Bottom Layer w0.4: S5.1@169.255,163.83 ccw(c169.255,162.85) 168.275,162.85 168.275,160.655 ccw(c169.545,160.655) 169.545,159.385 173.99,159.385 cw(c173.99,154.786) 177.242,158.038 D5.2@178.435,156.845
NetD6_2: D6.2 S6.1 | length 17
  Bottom Layer w0.4: S6.1@178.78,163.83 ccw(c178.78,162.85) 177.8,162.85 177.8,161.553 ccw(c179.968,161.553) 178.435,160.02 ccw(c179.968,161.553) 179.968,159.385 186.69,159.385 cw(c186.69,156.845) D6.2@189.23,156.845
NetD7_1: D7.1 L2.2 pad.1@107.95,125.095 Q14.2 | length 22.9
  Bottom Layer w1: pad.1@107.95,125.095 L2.2@107.95,126.79 cw(c110.065,126.79) 110.065,128.905 114.935,128.905 Q14.2@117.475,128.905 ccw(c117.475,131.445) 120.015,131.445 120.015,133.985 ccw(c117.475,133.985) D7.1@117.475,136.525
NetDS1_2: DS1.2 R44.1 | length 2.5
  Bottom Layer w0.4: R44.1@150.5,90.58 150.58,90.5 DS1.2@152.96,90.5
NetDS2_2: DS2.2 R45.1 | length 2.5
  Bottom Layer w0.4: R45.1@150.5,104.42 150.58,104.5 DS2.2@152.96,104.5
NetDS3_2: DS3.2 R46.1 | length 2.5
  Bottom Layer w0.4: R46.1@209.5,104.42 209.58,104.5 DS3.2@211.96,104.5
NetDS4_2: DS4.2 R47.1 | length 2.5
  Bottom Layer w0.4: R47.1@209.5,90.58 209.58,90.5 DS4.2@211.96,90.5
NetJ4_1: J4.1 R2.1 | length 24.6
  Top Layer w0.254: v1(240.03,144.78) v1(241.3,155.575)
  Bottom Layer w0.4: R2.1@232.41,160.655 236.22,160.655 cw(c236.22,155.575) v1(241.3,155.575) ; J4.1@238.125,144.78 v1(240.03,144.78)
NetLS1_2: LS1.2 Q5.3 | length 5.7
  Bottom Layer w0.4: Q5.3@241.935,139.7 241.935,140.936 cw(c246.761,140.936) 243.349,144.349 LS1.2@243.806,144.806
NetP2_1: P2.1 R10.2 | length 27.4
  Bottom Layer w0.5: P2.1@180,125 199.295,125 ccw(c199.295,130.175) R10.2@204.47,130.175
NetP2_2: P2.2 R14.1 | length 19.3
  Bottom Layer w0.5: P2.2@177.46,125 cw(c180.73,125) 180.73,128.27 191.516,128.27 ccw(c191.516,130.429) R14.1@193.675,130.429
NetP2_3: P2.3 R20.1 | length 11.1
  Bottom Layer w0.5: P2.3@174.92,125 cw(c180.349,125) 180.349,130.429 R20.1@182.88,130.429
NetP2_4: P2.4 R24.1 | length 5.6
  Bottom Layer w0.5: R24.1@172.085,130.429 172.38,130.134 P2.4@172.38,125
NetP2_5: P2.5 R29.1 | length 11.5
  Bottom Layer w0.5: R29.1@161.29,130.175 164.665,130.175 cw(c164.665,125) P2.5@169.84,125
NetP2_6: P2.6 R33.1 | length 19.8
  Bottom Layer w0.5: R33.1@150.495,130.175 ccw(c153.035,130.175) 153.035,127.635 164.665,127.635 cw(c164.665,125) P2.6@167.3,125
NetP2_7: P2.7 R38.1 | length 28
  Bottom Layer w0.5: R38.1@139.7,130.175 ccw(c144.875,130.175) 144.875,125 P2.7@164.76,125
NetP4_1: P4.1 V6.1 | length 84.2
  Bottom Layer w0.5: P4.1@180,77.5 196.214,77.5 ccw(c196.214,86.036) 202.25,80 202.805,80.555 cw(c207.5,75.861) 207.5,82.5 237.879,82.5 ccw(c237.879,87.621) 241.5,84 241.75,84.25 cw(c246.578,79.422) 246.578,86.25 256.418,86.25 ccw(c256.418,90.069) 259.119,87.369 ccw(c256.989,89.498) V6.1@260.001,89.498
NetP4_2: P4.2 V5.1 | length 63.9
  Bottom Layer w0.5: P4.2@177.46,77.5 cw(c179.98,77.5) 179.98,80.02 193.977,80.02 ccw(c193.977,88.573) 200.025,82.525 cw(c206,76.55) 206,85 231.502,85 ccw(c231.502,89.498) V5.1@236.001,89.498
NetP4_3: P4.3 V4.1 | length 32.9
  Bottom Layer w0.5: P4.3@174.92,77.5 cw(c179.92,77.5) 179.92,82.5 194.002,82.5 ccw(c194.002,89.498) V4.1@201.001,89.498
NetP4_4: P4.4 V3.1 | length 13.4
  Bottom Layer w0.4: P4.4@172.38,77.5 172.38,79 ; V3.1@177.001,88.87 V3.1@177.001,89.498
  Bottom Layer w0.5: 172.38,79 cw(c177.812,79) 173.971,82.841 174.88,83.75 ccw(c169.76,88.87) V3.1@177.001,88.87
NetP4_5: P4.5 V2.1 | length 34.7
  Bottom Layer w0.5: V2.1@142.001,89.498 ccw(c146.499,89.498) 146.499,85 162.34,85 cw(c162.34,77.5) P4.5@169.84,77.5
NetP4_6: P4.6 V1.1 | length 56.1
  Bottom Layer w0.5: V1.1@118.001,89.498 ccw(c124.999,89.498) 124.999,82.5 162.3,82.5 cw(c162.3,77.5) P4.6@167.3,77.5
NetP4_7: P4.7 R44.2 R45.2 R46.2 R47.2 | length 247.6
  Bottom Layer w0.5: 180,113 ccw(c176.186,109.186) 176.186,114.58 175.895,114.58 ; R47.2@209.5,80.42 208.327,79.247 cw(c199.885,87.688) 199.885,75.75 166.51,75.75 cw(c166.51,77.5) P4.7@164.76,77.5 164.76,77.88 ccw(c162.22,77.88) 162.22,80.42 R44.2@150.5,80.42 116.938,80.42 cw(c116.938,92.358) 105,92.358 105,102.642 cw(c116.938,102.642) 116.938,114.58 R45.2@150.5,114.58 175.895,114.58 ; R46.2@209.5,114.58 193.754,114.58 ccw(c193.754,108.712) 189.604,112.861 cw(c185.715,116.751) 185.715,111.25 183.932,111.25 ; 175.895,114.58 cw(c175.895,108.484) 180.205,112.795 180.207,112.793 ; 180.207,112.793 ccw(c183.932,116.518) 183.932,111.25 ; 180.207,112.793 ccw(c183.932,116.518) 183.932,111.25
NetQ1_2: Q1.2 R9.2 | length 2.5
  Bottom Layer w0.5: Q1.2@207.645,137.795 R9.2@210.185,137.795
NetQ1_3: Q1.3 R7.2 | length 4.1
  Bottom Layer w0.5: Q1.3@207.645,140.081 R7.2@207.645,144.145
NetQ2_1: Q2.1 R10.1 | length 2.5
  Bottom Layer w0.5: R10.1@204.47,140.335 Q2.1@204.47,142.875
NetQ2_3: Q2.3 R8.2 R9.1 | length 8.3
  Bottom Layer w0.5: Q2.3@204.47,147.955 R9.1@210.185,147.955 R8.2@212.725,147.955
NetQ3_2: Q3.2 R13.1 | length 2.5
  Bottom Layer w0.5: Q3.2@196.85,137.795 R13.1@199.39,137.795
NetQ3_3: Q3.3 R11.2 | length 4.1
  Bottom Layer w0.5: Q3.3@196.85,140.081 R11.2@196.85,144.145
NetQ4_1: Q4.1 R14.2 | length 2.3
  Bottom Layer w0.5: R14.2@193.675,140.589 Q4.1@193.675,142.875
NetQ4_3: Q4.3 R12.1 R13.2 | length 8.3
  Bottom Layer w0.5: Q4.3@193.675,147.955 R13.2@199.39,147.955 R12.1@201.93,147.955
NetQ5_2: Q5.2 R19.1 | length 3.8
  Bottom Layer w0.4: R19.1@241.3,135.255 cw(c244.366,135.255) 242.198,137.423 Q5.2@243.205,138.43
NetQ6_2: Q6.2 R17.1 | length 2.5
  Bottom Layer w0.5: Q6.2@186.055,137.795 R17.1@188.595,137.795
NetQ6_3: Q6.3 R15.2 | length 4.1
  Bottom Layer w0.5: Q6.3@186.055,140.081 R15.2@186.055,144.145
NetQ7_1: Q7.1 R20.2 | length 2.3
  Bottom Layer w0.5: R20.2@182.88,140.589 Q7.1@182.88,142.875
NetQ7_3: Q7.3 R16.1 R17.2 | length 8.3
  Bottom Layer w0.5: Q7.3@182.88,147.955 R17.2@188.595,147.955 R16.1@191.135,147.955
NetQ8_2: Q8.2 R23.1 | length 2.5
  Bottom Layer w0.5: Q8.2@175.26,137.795 R23.1@177.8,137.795
NetQ8_3: Q8.3 R21.2 | length 4.1
  Bottom Layer w0.5: Q8.3@175.26,140.081 R21.2@175.26,144.145
NetQ9_1: Q9.1 R24.2 | length 2.3
  Bottom Layer w0.5: R24.2@172.085,140.589 Q9.1@172.085,142.875
NetQ9_3: Q9.3 R22.1 R23.2 | length 8.3
  Bottom Layer w0.5: Q9.3@172.085,147.955 R23.2@177.8,147.955 R22.1@180.34,147.955
NetQ10_2: Q10.2 R27.1 | length 2.5
  Bottom Layer w0.5: Q10.2@164.465,137.795 R27.1@167.005,137.795
NetQ10_3: Q10.3 R25.2 | length 4.1
  Bottom Layer w0.5: Q10.3@164.465,140.081 R25.2@164.465,144.145
NetQ11_1: Q11.1 R29.2 | length 2.5
  Bottom Layer w0.5: R29.2@161.29,140.335 Q11.1@161.29,142.875
NetQ11_3: Q11.3 R26.1 R27.2 | length 8.3
  Bottom Layer w0.5: Q11.3@161.29,147.955 R27.2@167.005,147.955 R26.1@169.545,147.955
NetQ12_2: Q12.2 R32.1 | length 2.5
  Bottom Layer w0.5: Q12.2@153.67,137.795 R32.1@156.21,137.795
NetQ12_3: Q12.3 R30.2 | length 4.1
  Bottom Layer w0.5: Q12.3@153.67,140.081 R30.2@153.67,144.145
NetQ13_1: Q13.1 R33.2 | length 2.5
  Bottom Layer w0.5: R33.2@150.495,140.335 Q13.1@150.495,142.875
NetQ13_3: Q13.3 R31.1 R32.2 | length 8.3
  Bottom Layer w0.5: Q13.3@150.495,147.955 R32.2@156.21,147.955 R31.1@158.75,147.955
